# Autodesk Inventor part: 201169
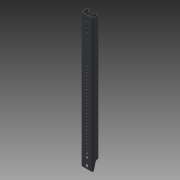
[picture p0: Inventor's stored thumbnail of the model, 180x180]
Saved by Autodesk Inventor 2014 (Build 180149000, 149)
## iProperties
Created: 2007-10
Part Number: 201169
Document SubType Name: Modeling
Designer: TH
Density: 8.08 g/cm^3
Mass: 849.269 g
Surface Area: 958.493 cm^2
Volume: 105.108 cm^3
Material: Stainless Steel
Description: BOTTOM RAIL
Appearance: Gray
Component Category: Lower Component
Author: TH
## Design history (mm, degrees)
sketch "Sketch1"
  geometry: L1 (-14.7, 0)-(14.7, 0); L2 (20, 5.3)-(20, 17.7); L3 (14.7, 23)-(14.511, 23); L4 (10.169, 20.74)-(6.758, 15.869); L5 (8.643, 14.55)-(12.053, 19.421); L6 (14.511, 20.7)-(14.7, 20.7); L7 (17.7, 17.7)-(17.7, 5.3); L8 (14.7, 2.3)-(-14.7, 2.3); L9 (-17.7, 5.3)-(-17.7, 17.7); L10 (-6.758, 15.869)-(-10.169, 20.74); L11 (-14.511, 23)-(-14.7, 23); L12 (-20, 17.7)-(-20, 5.3); L13 (-14.7, 20.7)-(-14.511, 20.7); L14 (-12.053, 19.421)-(-8.823, 14.808); L15 (5.8, 12)-(8.1, 12); L16 (8.1, 12)-(8.1, 12.829); L17 (5.8, 12)-(5.8, 12.829); L18 (-8.1, 12)-(-5.8, 12); L19 (-5.8, 12)-(-5.8, 12.829); L20 (-8.1, 12)-(-8.1, 12.514); A1 r 4 centre (-12.1, 12.514) between (-8.1, 12.514) and (-8.823, 14.808); A2 r 3 centre (-14.511, 17.7) between (-12.053, 19.421) and (-14.511, 20.7); A3 r 3 centre (-14.7, 17.7) between (-14.7, 20.7) and (-17.7, 17.7); A4 r 3 centre (-14.7, 5.3) between (-17.7, 5.3) and (-14.7, 2.3); A5 r 3 centre (14.7, 5.3) between (14.7, 2.3) and (17.7, 5.3); A6 r 3 centre (11.1, 12.829) between (8.643, 14.55) and (8.1, 12.829); A7 r 3 centre (14.511, 17.7) between (14.511, 20.7) and (12.053, 19.421); A8 r 3 centre (14.7, 17.7) between (17.7, 17.7) and (14.7, 20.7); A9 r 5.3 centre (-11.1, 12.829) between (-5.8, 12.829) and (-6.758, 15.869); A10 r 5.3 centre (-14.511, 17.7) between (-10.169, 20.74) and (-14.511, 23); A11 r 5.3 centre (-14.7, 17.7) between (-14.7, 23) and (-20, 17.7); A12 r 5.3 centre (-14.7, 5.3) between (-20, 5.3) and (-14.7, 0); A13 r 5.3 centre (14.7, 5.3) between (14.7, 0) and (20, 5.3); A14 r 5.3 centre (14.7, 17.7) between (20, 17.7) and (14.7, 23); A15 r 5.3 centre (14.511, 17.7) between (14.511, 23) and (10.169, 20.74); A16 r 5.3 centre (11.1, 12.829) between (6.758, 15.869) and (5.8, 12.829); 5 further points
  constraints: 40 end point, 32 point on circle, 32 tangent, 16 centre point, 13 equal radius, 10 parallel, 8 point on line, 6 perpendicular, 2 collinear, 1 horizontal, 1 midpoint
  dimensions: "d0" = 40 distance of point (-20, 0) point (20, 0); "d1" = 20 distance from line of point (0, 0) L2 (= 0.5 x d0); "d2" = 2.3 distance between parallel lines of L1 L8; "d3" = 2.3 distance between parallel lines of L2 L7 (= d2); "d4" = 2.3 distance between parallel lines of L3 L6 (= d2); "d5" = 2.3 distance between parallel lines of L4 L5 (= d2); "d6" = 2.3 distance between parallel lines of L12 L9 (= d2); "d7" = 2.3 distance of L18.start L18.end (= d2); "d9" = 2.3 distance of L15.start L15.end (= d2); "d10" = 35 deg angle of L7 L5; "d11" = 35 deg angle of L9 L14 (= d10); "d12" = 2.3 distance between parallel lines of L10 L14 (= d2); "d13" = 2.3 distance between parallel lines of L11 L13 (= d2); "d14" = 2.5 distance from line of point (5.8, 14.5) L15; "d15" = 2.5 distance of L18.end point (-5.8, 14.5) (= d14); "d16" = 23 distance between parallel lines of L1 L3; "d17" = 5.8 distance from line of point (0, 0) L17; "d18" = 5.8 distance from line of point (0, 0) L19 (= d17); "d19" = 12 distance between parallel lines of L1 L15; "d20" = 4 radius of A1; "d21" = 3 radius of A2; "d22" = 5.3 radius of A9
extrude "Extrusion1" new body sketch "Sketch1" distance "d23" = 456.5; taper "d24" = 0 deg
sketch "Sketch2"
  geometry: L1 (12, -456.5)-(12.829, -456.5) reference; L2 (12.829, -456.5)-(12, -456.5) reference; L3 (15.869, -456.5)-(12.829, -456.5) reference; L4 (20.74, -456.5)-(15.869, -456.5) reference; L5 (23, -456.5)-(20.74, -456.5) reference; L6 (17.7, -456.5)-(23, -456.5) reference; L7 (5.3, -456.5)-(17.7, -456.5) reference; L8 (0, -456.5)-(5.3, -456.5) reference; L9 (5.3, -456.5)-(0, -456.5) reference; L10 (17.7, -456.5)-(5.3, -456.5) reference; L11 (23, -456.5)-(17.7, -456.5) reference; L12 (20.74, -456.5)-(23, -456.5) reference; L13 (15.869, -456.5)-(20.74, -456.5) reference; L14 (12.829, -456.5)-(15.869, -456.5) reference; L15 (12, -456.5)-(12.829, -456.5) reference; L16 (12.514, -456.5)-(12, -456.5) reference; L17 (14.808, -456.5)-(12.514, -456.5) reference; L18 (19.421, -456.5)-(14.808, -456.5) reference; L19 (20.7, -456.5)-(19.421, -456.5) reference; L20 (17.7, -456.5)-(20.7, -456.5) reference; L21 (5.3, -456.5)-(17.7, -456.5) reference; L22 (2.3, -456.5)-(5.3, -456.5) reference; L23 (5.3, -456.5)-(2.3, -456.5) reference; L24 (17.7, -456.5)-(5.3, -456.5) reference; L25 (20.7, -456.5)-(17.7, -456.5) reference; L26 (19.421, -456.5)-(20.7, -456.5) reference; L27 (14.55, -456.5)-(19.421, -456.5) reference; L28 (12.829, -456.5)-(14.55, -456.5) reference; L29 (3.8, -456.5)-(11.838, -426.5); L30 (11.838, -426.5)-(23.8, -426.5); L31 (3.8, -456.5)-(23.8, -456.5); L32 (23.8, -456.5)-(23.8, -426.5); 2 further points
  constraints: 8 end point, 2 parallel, 1 midpoint, 1 perpendicular
  dimensions: "d25" = 20 distance of L29.start L31.end; "d26" = 75 deg angle of L10 L29; "d27" = 30 distance between parallel lines of L31 L30
extrude "Extrusion2" cut sketch "Sketch2" stored distance "d28" = 10; taper "d29" = 0 deg
fillet "Fillet1" dims "d30" = 6
fillet "Fillet2" dims "d31" = 2
sketch "Sketch3" dims "d45" = 10, "d52" = 10
  geometry: L1 (0, 456.5)-(29.4, 456.5) reference; L2 (18.775, 444.177)-(18.775, 450.227); L3 (10.625, 444.177)-(10.625, 450.227); L4 (14.7, 547.809)-(14.7, -91.302) reference; L5 (18.775, 30.975)-(18.775, 37.025); L6 (10.625, 30.975)-(10.625, 37.025); L7 (10.625, 9.925)-(10.625, 15.975); L8 (18.775, 9.925)-(18.775, 15.975); A1 r 5.075 centre (14.7, 447.202) between (18.775, 450.226) and (10.625, 450.226); A2 r 5.075 centre (14.7, 447.202) between (10.625, 444.177) and (18.775, 444.177); A3 r 5.075 centre (14.7, 34) between (18.775, 37.024) and (10.625, 37.024); A4 r 5.075 centre (14.7, 34) between (10.625, 30.975) and (18.775, 30.975); A5 r 5.075 centre (14.7, 12.95) between (18.775, 15.974) and (10.625, 15.974); A6 r 5.075 centre (14.7, 12.95) between (10.625, 9.925) and (18.775, 9.925); 1 further point
  constraints: 12 end point, 12 point on circle, 7 point on line, 6 centre point, 2 vertical, 1 parallel, 22 other
  dimensions: "d32" = 5.075 radius of A2; "d33" = 5.075 radius of A1; "d34" = 8.15002 distance between parallel lines of L2 L3; "d35" = 9.29809 distance from line of L1 A1.centre; "d37" = 4.07501 distance between parallel lines of L4 L2; "d42" = 413.202 distance of L2.end L5.end; "d49" = 21.05 distance of A3.centre A5.centre
extrude "Extrusion3" cut sketch "Sketch3" stored distance "d38" = 10; taper "d39" = 0 deg
workaxis "Work Axis1"
sketch "Sketch4"
  geometry: L1 (0, -456.5)-(29.4, -456.5) reference; L2 (11.7, -407)-(17.7, -407); L3 (18.7, -408)-(18.7, -411); L4 (17.7, -412)-(11.7, -412); L5 (10.7, -411)-(10.7, -408); A1 r 5.075 centre (14.7, -447.202) between (18.775, -444.177) and (10.625, -444.177) reference; A2 r 1 centre (11.7, -408) between (11.7, -407) and (10.7, -408); A3 r 1 centre (11.7, -411) between (10.7, -411) and (11.7, -412); A4 r 1 centre (17.7, -411) between (17.7, -412) and (18.7, -411); A5 r 1 centre (17.7, -408) between (18.7, -408) and (17.7, -407); 4 further points
  constraints: 8 end point, 8 point on circle, 8 tangent, 6 point on line, 4 centre point, 3 equal radius, 2 parallel, 1 horizontal, 1 perpendicular
  dimensions: "d54" = 8 distance of point (10.7, -407) point (18.7, -407); "d55" = 5 distance of point (10.7, -412) point (10.7, -407); "d56" = 4 distance from line of L5 A1.centre (= 0.5 x d54); "d57" = 44.5 distance between parallel lines of L1 L4; "d58" = 1 radius of A2
extrude "Extrusion4" cut sketch "Sketch4" stored distance "d59" = 10; taper "d60" = 0 deg
sketch "Sketch5"
  geometry: L1 (0, 0)-(0, -456.5) reference; L2 (14.7, -447.202)-(14.7, -422.702); L3 (14.7, -422.702)-(14.7, -46.702); A1 r 5.075 centre (14.7, -447.202) between (10.625, -450.226) and (18.775, -450.226) reference; 2 further points
  constraints: 4 end point, 2 parallel, 1 point on line
  dimensions: "d64" = 24.5 distance of L2.start L2.end; "d65" = 376 distance of L2.end L3.end; "d66" = 21 distance of L3.end point (14.7, -67.702)
hole "Hole1" sketch "Sketch5" diameter "d67" = 8; stored, may be unused: countersink angle "d71" = 90 deg, drill point angle "d73" = 118 deg; dims "d68" = 6, "d69" = 4, "d70" = 2, "d72" = 8
hole "Hole2" sketch "Sketch5" diameter "d74" = 10; stored, may be unused: countersink angle "d78" = 90 deg, drill point angle "d80" = 118 deg; dims "d75" = 6, "d76" = 4, "d77" = 2, "d79" = 8
body "Solid1"
pattern_linear "Rectangular Pattern1" dims "d63" = 10
node "Projected Loop1"
